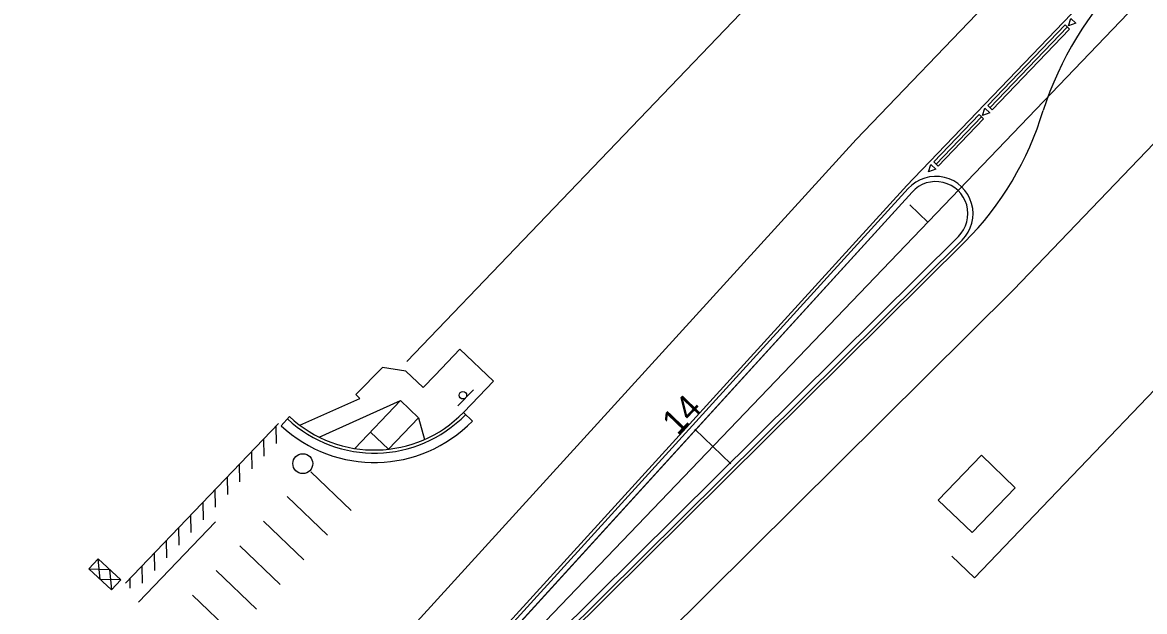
# Model space of a CAD drawing. Extents: x 2377903 to 2496516, y 664638 to 732785.
# Drawn here: x 2378076.4 to 2378256.9, y 730356.6 to 730451.4 of the extents above; entities that cross this region are included whole.
import ezdxf

# ---------------------------------------------------------------- set-up
doc = ezdxf.new("R2010")
doc.units = 0
for name, color, linetype in [('ALG_CL_BLUE_Horiz', 7, 'Continuous'), ('ALG_CL_BLUE_Horiz-Stationing', 7, 'Continuous'), ('DES_ROADWAY_Concrete-Pavement', 7, 'Continuous'), ('DES_ROADWAY_Curb-Back', 7, 'Continuous'), ('DES_ROADWAY_Curb-Face', 7, 'Continuous'), ('DES_ROADWAY_Curb-Face-LINE STYLE', 7, 'Continuous'), ('DES_ROADWAY_Edge-of-Pavement', 7, 'Continuous'), ('DES_ROADWAY_Misc-SAW CUT', 7, 'Continuous'), ('DES_ROADWAY_Sidewalk', 7, 'Continuous'), ('ENV_EROSN_Temp-Erosn-Ctrl-Details', 7, 'Continuous'), ('ROW_P_PUA', 7, 'Continuous'), ('TOPO_WTRUTIL_Valve', 7, 'Continuous'), ('TRAF_PAVEMARK_Stop-Bar', 7, 'Continuous'), ('TRAF_PAVEMARK_White_SKIP 12-38', 7, 'Continuous'), ('TRAF_PAVEMARK_Yellow', 7, 'Continuous'), ('TRAF_SIGN_Post', 7, 'Continuous'), ('TRAF_WORKZONE_Drum', 7, 'Continuous')]:
    doc.layers.add(name, color=color, linetype=linetype)

msp = doc.modelspace()

# ---------------------------------------------------------------- linework, layer by layer
at = {"layer": 'ALG_CL_BLUE_Horiz'}
msp.add_line((2378143.04, 730336.85), (2378375.43, 730579.33), dxfattribs=at)
at = {"layer": 'ALG_CL_BLUE_Horiz-Stationing'}
for p, q in [((2378219.16, 730422.05), (2378222.04, 730419.28)), ((2378184.56, 730385.95), (2378190.34, 730380.42))]:
    msp.add_line(p, q, dxfattribs=at)
at = {"layer": 'DES_ROADWAY_Concrete-Pavement'}
for p, q in [((2378087.64, 730279.33), (2378219.51, 730424.11)), ((2378226.97, 730416.96), (2378087.88, 730279.09))]:
    msp.add_line(p, q, dxfattribs=at)
msp.add_arc((2378223.33, 730420.63), 5.17, 314.7476, 137.6727, dxfattribs=at)
at = {"layer": 'DES_ROADWAY_Curb-Back'}
for p, q in [((2378244.51, 730450.67), (2378232.05, 730437.67)), ((2378230.67, 730436.23), (2378223.37, 730428.61)), ((2378219.51, 730424.11), (2378087.64, 730279.33)), ((2378087.88, 730279.09), (2378226.97, 730416.96)), ((2378118.01, 730386.53), (2378119.37, 730387.99)), ((2378147.35, 730388.67), (2378148.78, 730387.27))]:
    msp.add_line(p, q, dxfattribs=at)
for centre, radius, start, end in [((2378223.33, 730420.63), 5.17, 314.7476, 137.6727), ((2378133.01, 730402.62), 20, 226.9933, 315.7778)]:
    msp.add_arc(centre, radius, start, end, dxfattribs=at)
at = {"layer": 'DES_ROADWAY_Curb-Face'}
for p, q in [((2378244.14, 730451.01), (2378231.69, 730438.02)), ((2378244.14, 730451.01), (2378244.87, 730450.32)), ((2378244.87, 730450.32), (2378232.41, 730437.33)), ((2378230.31, 730436.58), (2378223, 730428.96)), ((2378230.31, 730436.58), (2378231.03, 730435.88)), ((2378231.69, 730438.02), (2378232.41, 730437.33)), ((2378231.03, 730435.88), (2378223.73, 730428.27)), ((2378223, 730428.96), (2378223.73, 730428.27))]:
    msp.add_line(p, q, dxfattribs=at)
at = {"layer": 'DES_ROADWAY_Curb-Face-LINE STYLE'}
msp.add_arc((2378133.01, 730402.62), 20.5, 226.9933, 315.7778, dxfattribs=at)
at = {"layer": 'DES_ROADWAY_Edge-of-Pavement'}
for p, q in [((2378218.91, 730424.68), (2378087.03, 730279.89)), ((2378088.47, 730278.5), (2378227.57, 730416.38)), ((2378092.96, 730361.19), (2378117.6, 730386.9))]:
    msp.add_line(p, q, dxfattribs=at)
for centre, radius, start, end in [((2378223.33, 730420.63), 6, 314.9377, 137.4827), ((2378133.01, 730402.62), 22, 226.9933, 315.7778)]:
    msp.add_arc(centre, radius, start, end, dxfattribs=at)
at = {"layer": 'DES_ROADWAY_Misc-SAW CUT'}
for p, q in [((2378117.26, 730383.66), (2378117.2, 730386.49)), ((2378115.3, 730381.62), (2378115.24, 730384.44)), ((2378113.35, 730379.57), (2378113.29, 730382.4)), ((2378111.39, 730377.53), (2378111.33, 730380.36)), ((2378109.43, 730375.49), (2378109.37, 730378.32)), ((2378107.47, 730373.45), (2378107.41, 730376.27)), ((2378105.52, 730371.4), (2378105.46, 730374.23)), ((2378103.56, 730369.36), (2378103.5, 730372.19)), ((2378101.6, 730367.32), (2378101.54, 730370.15)), ((2378099.64, 730365.28), (2378099.58, 730368.11)), ((2378097.69, 730363.23), (2378097.63, 730366.06)), ((2378095.73, 730361.19), (2378095.67, 730364.02)), ((2378093.74, 730360.42), (2378093.71, 730361.98))]:
    msp.add_line(p, q, dxfattribs=at)
at = {"layer": 'DES_ROADWAY_Sidewalk'}
for p, q in [((2378146.78, 730398.85), (2378142.78, 730394.67)), ((2378152.17, 730393.69), (2378146.78, 730398.85)), ((2378130.05, 730391.56), (2378134.31, 730395.88)), ((2378138.06, 730395.32), (2378134.31, 730395.88)), ((2378138.06, 730395.32), (2378140.84, 730392.65)), ((2378140.84, 730392.65), (2378142.78, 730394.67)), ((2378152.17, 730393.69), (2378148.64, 730390)), ((2378130.05, 730391.56), (2378130.69, 730390.92)), ((2378121.04, 730386.6), (2378130.69, 730390.92)), ((2378124.14, 730384.69), (2378137.23, 730390.57)), ((2378129.85, 730382.87), (2378137.23, 730390.57)), ((2378137.23, 730390.57), (2378140.12, 730387.8)), ((2378148.64, 730390), (2378147.35, 730388.67)), ((2378135.28, 730382.75), (2378140.12, 730387.8)), ((2378140.12, 730387.8), (2378141.07, 730384.31)), ((2378132.39, 730385.51), (2378135.28, 730382.75)), ((2378230.66, 730381.79), (2378223.73, 730374.57)), ((2378236.11, 730376.56), (2378230.66, 730381.79)), ((2378229.18, 730369.35), (2378236.11, 730376.56)), ((2378229.18, 730369.35), (2378223.73, 730374.57))]:
    msp.add_line(p, q, dxfattribs=at)
at = {"layer": 'ENV_EROSN_Temp-Erosn-Ctrl-Details'}
msp.add_lwpolyline([(2378090.71, 730360.11), (2378087.06, 730363.53), (2378088.56, 730365.14), (2378092.21, 730361.72)], close=True, dxfattribs=at)
for points in [[(2378092.21, 730361.72), (2378088.88, 730361.82), (2378088.56, 730365.14)], [(2378087.06, 730363.53), (2378090.39, 730363.43), (2378090.71, 730360.11)]]:
    msp.add_lwpolyline(points, dxfattribs=at)
at = {"layer": 'ROW_P_PUA'}
for p, q in [((2378138.22, 730396.85), (2378218.62, 730480.74)), ((2378229.54, 730362.07), (2378277.37, 730411.97)), ((2378229.54, 730362.07), (2378225.93, 730365.53))]:
    msp.add_line(p, q, dxfattribs=at)
at = {"layer": 'TOPO_WTRUTIL_Valve'}
msp.add_circle((2378121.5, 730380.43), 1.6, dxfattribs=at)
at = {"layer": 'TRAF_PAVEMARK_Stop-Bar'}
for p, q in [((2378122.79, 730379.12), (2378129.29, 730372.89)), ((2378118.99, 730375.15), (2378125.48, 730368.92)), ((2378095.07, 730358.15), (2378107.46, 730371.07)), ((2378115.18, 730371.18), (2378121.68, 730364.95)), ((2378111.37, 730367.21), (2378117.87, 730360.98)), ((2378107.57, 730363.24), (2378114.06, 730357.01)), ((2378103.76, 730359.27), (2378110.26, 730353.04))]:
    msp.add_line(p, q, dxfattribs=at)
at = {"layer": 'TRAF_PAVEMARK_White_SKIP 12-38'}
for p, q in [((2378329.94, 730557.15), (2378210.52, 730432.55)), ((2378351.49, 730529.06), (2378235.84, 730408.38)), ((2378210.52, 730432.55), (2378065.28, 730273.09)), ((2378082.74, 730256.63), (2378235.84, 730408.38))]:
    msp.add_line(p, q, dxfattribs=at)
at = {"layer": 'TRAF_PAVEMARK_Yellow'}
for p, q in [((2378321.66, 730532.62), (2378218.56, 730425.04)), ((2378218.65, 730425.15), (2378073.42, 730265.68)), ((2378074.99, 730264.44), (2378227.99, 730416.1))]:
    msp.add_line(p, q, dxfattribs=at)
for centre, radius, start, end in [((2378292.72, 730420.41), 54.76, 135.1259, 162.0922), ((2378192.49, 730451.63), 50.23, 314.978, 343.3604)]:
    msp.add_arc(centre, radius, start, end, dxfattribs=at)
at = {"layer": 'TRAF_SIGN_Post'}
msp.add_line((2378148.94, 730392.32), (2378146.45, 730389.72), dxfattribs=at)
msp.add_circle((2378147.26, 730391.43), 0.6, dxfattribs=at)
at = {"layer": 'TRAF_WORKZONE_Drum'}
for points in [[(2378244.68, 730450.85), (2378245.05, 730452.05), (2378245.86, 730451.27)], [(2378230.84, 730436.41), (2378231.21, 730437.61), (2378232.02, 730436.83)], [(2378222.15, 730427.35), (2378222.53, 730428.55), (2378223.34, 730427.77)]]:
    msp.add_lwpolyline(points, close=True, dxfattribs=at)

# ---------------------------------------------------------------- texts
at = {"layer": 'ALG_CL_BLUE_Horiz-Stationing'}
msp.add_text('14', height=4, rotation=46.217, dxfattribs=at).set_placement((2378181.81, 730384.82))

doc.saveas('drawing.dxf')
